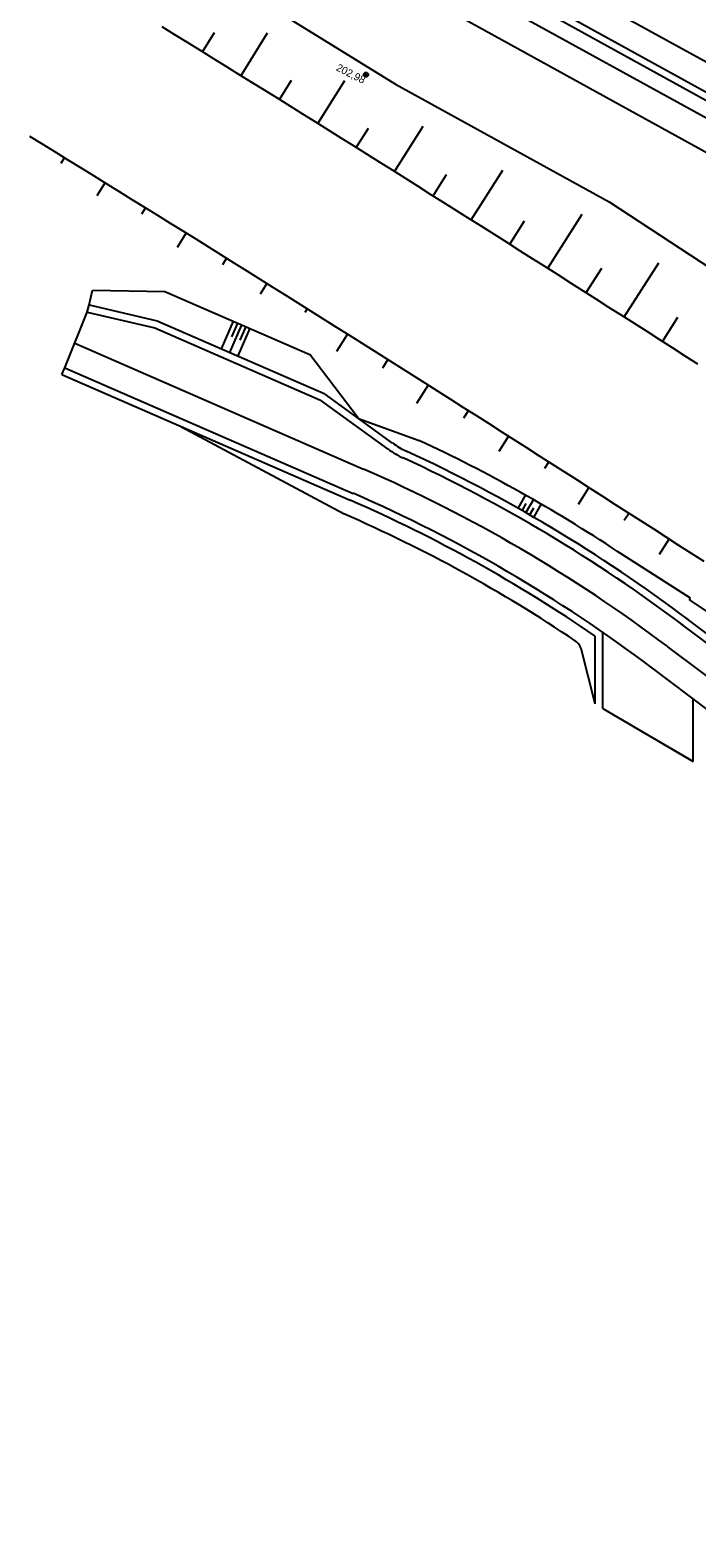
# Model space of a CAD drawing. Extents: x -552278 to -547230, y -1151007 to -1148251.
# Drawn here: x -550306.9 to -550262.6, y -1149128.4 to -1149028.3 of the extents above; entities that cross this region are included whole.
import ezdxf

# ---------------------------------------------------------------- set-up
doc = ezdxf.new("R2010")
doc.units = 0
doc.layers.add('SO221815_VYSKOPIS', color=7, linetype='Continuous')
doc.layers.add('u_trat navrh', color=7, linetype='Continuous')

# ---------------------------------------------------------------- blocks, each defined once
blk = doc.blocks.new('SO221824_VYSKOPIS')
at = {"layer": 'SO221815_VYSKOPIS'}
for p, q in [((1.2, -0.9), (-1.2, 0.9)), ((0.9, 1.2), (-0.9, -1.2)), ((0.9, 1.2), (0, 0)), ((0, 0), (1.2, -0.9))]:
    blk.add_line(p, q, dxfattribs=at)
blk.add_lwpolyline([(-0.9, -1.2), (0, 0), (-1.2, 0.9)], dxfattribs=at)
blk.add_circle((0, 0), 1.5, dxfattribs=at)
for start, end in [(145.362, 235.1538), (325.362, 55.1538)]:
    blk.add_arc((0, 0), 1.5, start, end, dxfattribs=at)

msp = doc.modelspace()

# ---------------------------------------------------------------- linework, layer by layer
at = {"layer": 'u_trat navrh'}
for p, q in [((-550460.23, -1148921.16), (-550253.98, -1149034.78)), ((-550461.07, -1148922.69), (-550254.82, -1149036.32)), ((-550461.8, -1148924.01), (-550255.55, -1149037.63)), ((-550462.76, -1148925.76), (-550256.51, -1149039.38)), ((-550306.47, -1149017.11), (-550282.62, -1149031.85)), ((-550295.44, -1149029.69), (-550294.65, -1149028.41)), ((-550292.88, -1149031.27), (-550291.12, -1149028.43)), ((-550290.33, -1149032.86), (-550289.53, -1149031.58)), ((-550287.78, -1149034.45), (-550285.99, -1149031.6)), ((-550282.62, -1149031.85), (-550268.44, -1149039.66)), ((-550285.23, -1149036.05), (-550284.42, -1149034.76)), ((-550282.68, -1149037.65), (-550280.79, -1149034.64)), ((-550304.6, -1149036.72), (-550304.85, -1149037.11)), ((-550280.13, -1149039.25), (-550279.24, -1149037.83)), ((-550277.59, -1149040.85), (-550275.5, -1149037.55)), ((-550301.91, -1149038.38), (-550302.45, -1149039.26)), ((-550268.44, -1149039.66), (-550240.61, -1149057.89)), ((-550299.22, -1149040.05), (-550299.48, -1149040.47)), ((-550272.5, -1149044.07), (-550270.22, -1149040.47)), ((-550296.53, -1149041.72), (-550297.13, -1149042.68)), ((-550275.04, -1149042.46), (-550274.06, -1149040.91)), ((-550293.85, -1149043.4), (-550294.12, -1149043.84)), ((-550267.43, -1149047.3), (-550265.13, -1149043.7)), ((-550269.97, -1149045.68), (-550268.92, -1149044.05)), ((-550302.97, -1149046.5), (-550302.75, -1149045.53)), ((-550302.75, -1149045.53), (-550297.94, -1149045.6)), ((-550297.94, -1149045.6), (-550288.31, -1149049.79)), ((-550291.16, -1149045.07), (-550291.61, -1149045.79)), ((-550303.09, -1149046.99), (-550302.97, -1149046.5)), ((-550302.97, -1149046.5), (-550298.45, -1149047.55)), ((-550288.48, -1149046.76), (-550288.64, -1149047)), ((-550304.58, -1149050.67), (-550303.09, -1149046.99)), ((-550303.09, -1149046.99), (-550298.61, -1149048.03)), ((-550298.45, -1149047.55), (-550287.36, -1149052.39)), ((-550293.4, -1149047.58), (-550294.2, -1149049.41)), ((-550292.85, -1149047.82), (-550293.65, -1149049.65)), ((-550293.12, -1149047.7), (-550293.52, -1149048.61)), ((-550264.89, -1149048.92), (-550263.87, -1149047.31)), ((-550298.61, -1149048.03), (-550287.61, -1149052.82)), ((-550292.3, -1149048.05), (-550293.1, -1149049.89)), ((-550292.57, -1149047.94), (-550292.97, -1149048.85)), ((-550285.8, -1149048.44), (-550286.53, -1149049.59)), ((-550303.92, -1149049.04), (-550284.74, -1149057.4)), ((-550285.07, -1149054.05), (-550288.31, -1149049.79)), ((-550304.77, -1149051.13), (-550304.58, -1149050.67)), ((-550304.58, -1149050.67), (-550285.44, -1149059.01)), ((-550283.13, -1149050.13), (-550283.49, -1149050.7)), ((-550304.77, -1149051.13), (-550285.64, -1149059.47)), ((-550280.45, -1149051.82), (-550281.23, -1149053.05)), ((-550283.12, -1149056.08), (-550287.61, -1149052.82)), ((-550282.82, -1149055.67), (-550287.36, -1149052.39)), ((-550277.78, -1149053.51), (-550278.1, -1149054.01)), ((-550296.87, -1149054.57), (-550286.04, -1149060.38)), ((-550285.07, -1149054.05), (-550281.06, -1149055.5)), ((-550275.11, -1149055.21), (-550275.75, -1149056.22)), ((-550272.44, -1149056.91), (-550272.73, -1149057.36)), ((-550269.78, -1149058.62), (-550270.5, -1149059.75)), ((-550273.98, -1149059.11), (-550274.48, -1149059.97)), ((-550273.97, -1149059.69), (-550274.22, -1149060.12)), ((-550273.46, -1149059.41), (-550273.96, -1149060.27)), ((-550272.94, -1149059.71), (-550273.44, -1149060.57)), ((-550273.45, -1149059.99), (-550273.7, -1149060.42)), ((-550267.11, -1149060.33), (-550267.43, -1149060.82)), ((-550263.04, -1149065.97), (-550267.87, -1149062.87)), ((-550264.45, -1149062.04), (-550265.12, -1149063.07)), ((-550263.1, -1149066.08), (-550263.04, -1149065.97)), ((-550248.9, -1149075.55), (-550263.1, -1149066.08)), ((-550191.52, -1149121.99), (-550263.62, -1149067.69)), ((-550191.22, -1149121.59), (-550263.32, -1149067.29)), ((-550269.36, -1149072.99), (-550269.36, -1149068.5)), ((-550268.86, -1149073.29), (-550268.86, -1149068.23)), ((-550269.36, -1149072.99), (-550270.27, -1149069.39)), ((-550185.98, -1149128.35), (-550264.54, -1149069.19)), ((-550193.63, -1149124.78), (-550265.73, -1149070.49)), ((-550262.86, -1149076.82), (-550262.86, -1149072.65)), ((-550268.86, -1149073.29), (-550262.86, -1149076.82)), ((-550262.86, -1149076.82), (-550266.31, -1149074.79))]:
    msp.add_line(p, q, dxfattribs=at)
for points in [[(-550255.07, -1149036.76), (-550461.31, -1148923.13)], [(-550298.15, -1149028.01), (-550297.3, -1149028.54), (-550296.45, -1149029.06), (-550295.6, -1149029.59), (-550294.75, -1149030.12), (-550293.9, -1149030.64), (-550293.04, -1149031.17), (-550292.19, -1149031.7), (-550291.34, -1149032.23), (-550290.49, -1149032.76), (-550289.64, -1149033.29), (-550288.79, -1149033.82), (-550287.94, -1149034.35), (-550287.1, -1149034.88), (-550286.25, -1149035.41), (-550285.4, -1149035.94), (-550284.55, -1149036.47), (-550283.7, -1149037.01), (-550282.85, -1149037.54), (-550282, -1149038.07), (-550281.16, -1149038.6), (-550280.31, -1149039.14), (-550279.46, -1149039.67), (-550278.61, -1149040.2), (-550277.77, -1149040.74), (-550276.92, -1149041.27), (-550276.07, -1149041.81), (-550275.23, -1149042.34), (-550274.38, -1149042.88), (-550273.54, -1149043.42), (-550272.69, -1149043.95), (-550271.85, -1149044.49), (-550271, -1149045.03), (-550270.16, -1149045.56), (-550269.31, -1149046.1), (-550268.47, -1149046.64), (-550267.62, -1149047.18), (-550266.78, -1149047.72), (-550265.93, -1149048.25), (-550265.09, -1149048.79), (-550264.25, -1149049.33), (-550263.4, -1149049.87), (-550262.56, -1149050.41)], [(-550306.93, -1149035.29), (-550306.08, -1149035.81), (-550305.23, -1149036.33), (-550304.38, -1149036.86), (-550303.53, -1149037.38), (-550302.68, -1149037.91), (-550301.83, -1149038.43), (-550300.98, -1149038.96), (-550300.13, -1149039.49), (-550299.28, -1149040.01), (-550298.43, -1149040.54), (-550297.58, -1149041.07), (-550296.74, -1149041.59), (-550295.89, -1149042.12), (-550295.04, -1149042.65), (-550294.19, -1149043.18), (-550293.35, -1149043.71), (-550292.5, -1149044.24), (-550291.65, -1149044.77), (-550290.81, -1149045.3), (-550289.96, -1149045.83), (-550289.11, -1149046.36), (-550288.27, -1149046.89), (-550287.42, -1149047.42), (-550286.58, -1149047.95), (-550285.73, -1149048.48), (-550284.89, -1149049.02), (-550284.04, -1149049.55), (-550283.2, -1149050.08), (-550282.35, -1149050.62), (-550281.51, -1149051.15), (-550280.67, -1149051.68), (-550279.82, -1149052.22), (-550278.98, -1149052.75), (-550278.14, -1149053.29), (-550277.29, -1149053.82), (-550276.45, -1149054.36), (-550275.61, -1149054.9), (-550274.76, -1149055.43), (-550273.92, -1149055.97), (-550273.08, -1149056.51), (-550272.24, -1149057.04), (-550271.4, -1149057.58), (-550270.56, -1149058.12), (-550269.71, -1149058.66), (-550268.87, -1149059.2), (-550268.03, -1149059.74), (-550267.19, -1149060.27), (-550266.35, -1149060.81), (-550265.51, -1149061.35), (-550264.67, -1149061.9), (-550263.83, -1149062.44), (-550262.99, -1149062.98), (-550262.15, -1149063.52)]]:
    msp.add_lwpolyline(points, dxfattribs=at)
for centre, radius, start, end in [((-550279.6, -1149051.21), 5.5, 234.1181, 245.2578), ((-550324.7, -1149149.07), 103.25, 56.6068, 65.001), ((-550279.6, -1149051.21), 6, 234.1181, 245.2578), ((-550324.7, -1149149.07), 101.75, 53.0187, 65.2578), ((-550324.7, -1149149.07), 102.25, 53.0187, 65.2578), ((-550324.7, -1149149.07), 100, 53.0187, 66.4494), ((-550324.7, -1149149.07), 97.75, 55.5199, 66.4494), ((-550324.7, -1149149.07), 98.25, 53.0187, 66.4494), ((-550324.7, -1149149.07), 96.75, 56.0596, 66.4494), ((-550271.24, -1149069.64), 1, 14.1652, 56.0596)]:
    msp.add_arc(centre, radius, start, end, dxfattribs=at)

# ---------------------------------------------------------------- block references
at = {"layer": 'u_trat navrh', "xscale": 0.1, "yscale": 0.09999999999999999, "rotation": -31.851985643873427}
msp.add_blockref('SO221824_VYSKOPIS', (-550284.58, -1149031.21), dxfattribs=at)

# ---------------------------------------------------------------- texts
at = {"layer": 'u_trat navrh'}
msp.add_text('202,98', height=0.5, rotation=333.2568, dxfattribs=at).set_placement((-550286.61, -1149030.91))

doc.saveas('drawing.dxf')
